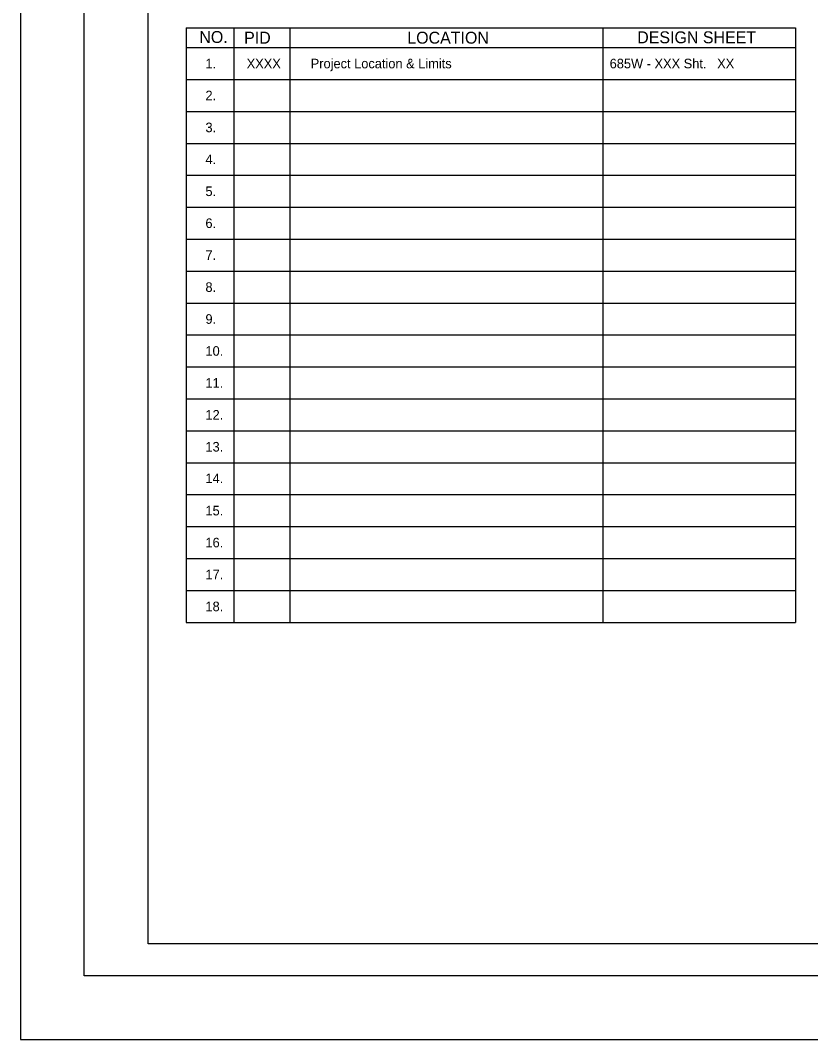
# Model space of a CAD drawing. Extents: x 105094 to 105814, y -291615 to -291123.
# Drawn here: x 105094.1 to 105341.6, y -291608.4 to -291289.2 of the extents above; entities that cross this region are included whole.
import ezdxf

# ---------------------------------------------------------------- set-up
doc = ezdxf.new("R2010")
doc.units = 0
doc.layers.add('G_BORDER', color=7, linetype='Continuous')
doc.layers.add('G_SHEET_EDGE', color=7, linetype='Continuous')

msp = doc.modelspace()

# ---------------------------------------------------------------- linework, layer by layer
at = {"layer": 'G_BORDER'}
for p, q in [((105146.1, -291291.56), (105336.89, -291291.56)), ((105146.1, -291291.56), (105146.1, -291477.75)), ((105161.04, -291291.56), (105161.04, -291477.75)), ((105178.51, -291291.56), (105178.51, -291477.75)), ((105276.55, -291291.56), (105276.55, -291477.75)), ((105336.89, -291291.56), (105336.89, -291477.75)), ((105146.1, -291297.75), (105336.89, -291297.75)), ((105146.1, -291307.75), (105336.89, -291307.75)), ((105146.1, -291317.75), (105336.89, -291317.75)), ((105146.1, -291327.75), (105336.89, -291327.75)), ((105146.1, -291337.75), (105336.89, -291337.75)), ((105146.1, -291347.75), (105336.89, -291347.75)), ((105146.1, -291357.75), (105336.89, -291357.75)), ((105146.1, -291367.75), (105336.89, -291367.75)), ((105146.1, -291377.75), (105336.89, -291377.75)), ((105146.1, -291387.75), (105336.89, -291387.75)), ((105146.1, -291397.75), (105336.89, -291397.75)), ((105146.1, -291407.75), (105336.89, -291407.75)), ((105146.1, -291417.75), (105336.89, -291417.75)), ((105146.1, -291427.75), (105336.89, -291427.75)), ((105146.1, -291437.75), (105336.89, -291437.75)), ((105146.1, -291447.75), (105336.89, -291447.75)), ((105146.1, -291457.75), (105336.89, -291457.75)), ((105146.1, -291467.75), (105336.89, -291467.75)), ((105146.1, -291477.75), (105336.89, -291477.75))]:
    msp.add_line(p, q, dxfattribs=at)
msp.add_lwpolyline([(105134.14, -291158.4), (105784.14, -291158.4), (105784.14, -291578.4), (105134.14, -291578.4)], close=True, dxfattribs=at)
at = {"layer": 'G_SHEET_EDGE'}
for points in [[(105094.14, -291608.4), (105814.14, -291608.4), (105814.14, -291128.4), (105094.14, -291128.4)], [(105114.14, -291148.4), (105794.14, -291148.4), (105794.14, -291588.4), (105114.14, -291588.4)]]:
    msp.add_lwpolyline(points, close=True, dxfattribs=at)

# ---------------------------------------------------------------- texts
at = {"layer": 'G_BORDER'}
for s, height, p in [('NO.', 3.741, (105150.18, -291296.31)), ('PID', 3.741, (105164.21, -291296.53)), ('LOCATION', 3.741, (105215.31, -291296.53)), ('DESIGN SHEET', 3.7405, (105287.32, -291296.41)), ('1.', 3, (105152.1, -291304.25)), ('XXXX', 3, (105165.01, -291304.25)), ('Project Location & Limits', 3, (105185.07, -291304.25)), ('685W - XXX Sht.   XX', 3, (105278.7, -291304.25)), ('2.', 3, (105152.1, -291314.25)), ('3.', 3, (105152.1, -291324.25)), ('4.', 3, (105152.1, -291334.25)), ('5.', 3, (105152.1, -291344.25)), ('6.', 3, (105152.1, -291354.25)), ('7.', 3, (105152.1, -291364.25)), ('8.', 3, (105152.1, -291374.25)), ('9.', 3, (105152.1, -291384.25)), ('10.', 3, (105152.1, -291394.25)), ('11.', 3, (105152.1, -291404.25)), ('12.', 3, (105152.1, -291414.25)), ('13.', 3, (105152.1, -291424.25)), ('14.', 3, (105152.1, -291434.14)), ('15.', 3, (105152.1, -291444.25)), ('16.', 3, (105152.1, -291454.25)), ('17.', 3, (105152.1, -291464.25)), ('18.', 3, (105152.1, -291474.25))]:
    msp.add_text(s, height=height, dxfattribs=at).set_placement(p)

doc.saveas('drawing.dxf')
